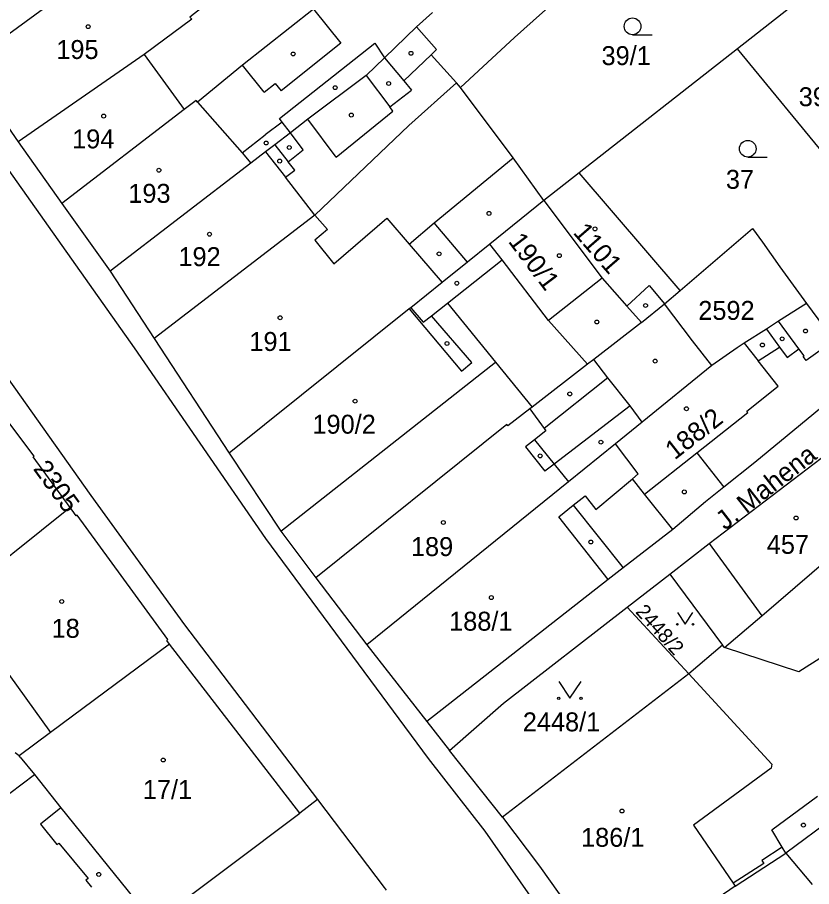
# Model space of a CAD drawing. Extents: x -679220 to -673243, y -1075091 to -1066557.
# Drawn here: x -676495.5 to -676424.2, y -1071396.5 to -1071318.5 of the extents above; entities that cross this region are included whole.
import ezdxf

# ---------------------------------------------------------------- set-up
doc = ezdxf.new("R2010")
doc.units = 0
for name, color, linetype in [('Hranice parcel', 7, 'Continuous'), ('Parcelní čísla', 7, 'Continuous'), ('Pop  PČ popisy', 7, 'Continuous'), ('Vnitřní kresba', 7, 'Continuous'), ('Značky budov', 7, 'Continuous'), ('Značky kultur', 7, 'Continuous')]:
    doc.layers.add(name, color=color, linetype=linetype)

msp = doc.modelspace()

# ---------------------------------------------------------------- linework, layer by layer
at = {"layer": 'Hranice parcel'}
for p, q in [((-676426.2, -1071317.64), (-676430.88, -1071321.3)), ((-676459.7, -1071319.33), (-676458.28, -1071318.06)), ((-676430.88, -1071321.3), (-676445.12, -1071332.45)), ((-676420.79, -1071333.62), (-676430.88, -1071321.3)), ((-676500.22, -1071322.85), (-676495.45, -1071329.66)), ((-676455.75, -1071324.77), (-676456.12, -1071324.37)), ((-676495.45, -1071329.66), (-676491.54, -1071335.21)), ((-676445.12, -1071332.45), (-676448.29, -1071334.93)), ((-676436.05, -1071343.02), (-676445.12, -1071332.45)), ((-676491.54, -1071335.21), (-676487.2, -1071341.29)), ((-676487.2, -1071341.29), (-676483.24, -1071347.33)), ((-676437.44, -1071344.22), (-676436.05, -1071343.02)), ((-676439.51, -1071345.88), (-676437.44, -1071344.22)), ((-676483.24, -1071347.33), (-676476.51, -1071357.62)), ((-676440.79, -1071371.46), (-676436.97, -1071368.48)), ((-676436.97, -1071368.48), (-676432.25, -1071374.85)), ((-676468.73, -1071368.83), (-676464.17, -1071374.82)), ((-676435.26, -1071377.43), (-676440.79, -1071371.46)), ((-676470.18, -1071389.94), (-676481.89, -1071374.77)), ((-676464.17, -1071374.82), (-676458.79, -1071381.72)), ((-676432.25, -1071374.85), (-676435.26, -1071377.43)), ((-676432.05, -1071375.08), (-676432.25, -1071374.85)), ((-676435.26, -1071377.43), (-676452, -1071390.3)), ((-676458.79, -1071381.72), (-676456.74, -1071384.32)), ((-676452, -1071390.3), (-676456.74, -1071384.32)), ((-676468.6, -1071388.71), (-676470.18, -1071389.94))]:
    msp.add_line(p, q, dxfattribs=at)
for points in [[(-676400.64, -1071480.43), (-676404.65, -1071473.51), (-676415.78, -1071453.37), (-676425.35, -1071436.91), (-676444.25, -1071404.92), (-676453.53, -1071391.57), (-676458.63, -1071385.05), (-676473.24, -1071365.27), (-676485.03, -1071348.15), (-676497.15, -1071331.02), (-676507.56, -1071316.17), (-676512.86, -1071309.51), (-676528.01, -1071291.25), (-676530.94, -1071288.81)], [(-676477.43, -1071306.13), (-676481.2, -1071308.93), (-676500.22, -1071322.85)], [(-676436.69, -1071307.58), (-676450.91, -1071320.28), (-676455.75, -1071324.77)], [(-676472.66, -1071312.61), (-676476.74, -1071315.84), (-676480.05, -1071318.46), (-676479.87, -1071318.65), (-676483.21, -1071321.14), (-676484.16, -1071321.81), (-676495.45, -1071329.66)], [(-676463.23, -1071313.31), (-676464.89, -1071314.65), (-676468.96, -1071317.75), (-676475.31, -1071322.79), (-676479.35, -1071326.09), (-676479.48, -1071325.94), (-676480.56, -1071326.77), (-676491.54, -1071335.21)], [(-676459.7, -1071319.33), (-676462.58, -1071322.11), (-676464.23, -1071323.7), (-676469.45, -1071327.64), (-676471.02, -1071328.86), (-676472.42, -1071329.92), (-676473.25, -1071330.56), (-676474.57, -1071331.57), (-676487.2, -1071341.29)], [(-676456.12, -1071324.37), (-676458.39, -1071321.84), (-676457.91, -1071321.38), (-676459.7, -1071319.33)], [(-676456.12, -1071324.37), (-676460.4, -1071328.18), (-676468.84, -1071336.26), (-676483.24, -1071347.33)], [(-676448.29, -1071334.93), (-676451.02, -1071331.11), (-676455.75, -1071324.77)], [(-676448.29, -1071334.93), (-676453.12, -1071338.84), (-676455.14, -1071340.47), (-676457.39, -1071342.3), (-676460.21, -1071344.56)], [(-676448.29, -1071334.93), (-676443.04, -1071341.91), (-676440.82, -1071344.41), (-676439.51, -1071345.88)], [(-676505.99, -1071337.37), (-676488.95, -1071361.42), (-676480.52, -1071373.04), (-676468.6, -1071388.71)], [(-676436.05, -1071343.02), (-676429.56, -1071337.44), (-676428.66, -1071338.68), (-676427.09, -1071340.88), (-676424.71, -1071344.18)], [(-676490.8, -1071362.5), (-676494.11, -1071357.94), (-676494.03, -1071357.88), (-676498.86, -1071351.49), (-676498.95, -1071351.57), (-676502.59, -1071346.77), (-676504.55, -1071344.1)], [(-676460.21, -1071344.56), (-676459.12, -1071345.87), (-676458.37, -1071345.28), (-676456.93, -1071344.14), (-676452.61, -1071349.45), (-676449.33, -1071353.49)], [(-676433.19, -1071349.75), (-676434.92, -1071347.53), (-676437.44, -1071344.22)], [(-676424.71, -1071344.18), (-676427.2, -1071345.77), (-676428.29, -1071346.48), (-676430.29, -1071347.75), (-676430.92, -1071348.16), (-676433.19, -1071349.75)], [(-676424.71, -1071344.18), (-676422.26, -1071347.51), (-676419.93, -1071350.69)], [(-676460.21, -1071344.56), (-676460.35, -1071344.67), (-676476.51, -1071357.62)], [(-676439.51, -1071345.88), (-676443.8, -1071349.21), (-676444.36, -1071349.64), (-676449.33, -1071353.49)], [(-676433.19, -1071349.75), (-676439.44, -1071354.83), (-676441.85, -1071356.78)], [(-676419.93, -1071350.69), (-676429.34, -1071358.47), (-676432.11, -1071360.68), (-676433.76, -1071362), (-676436.71, -1071364.46)], [(-676449.33, -1071353.49), (-676449.53, -1071353.65), (-676451.51, -1071355.18), (-676451.6, -1071355.06), (-676468.73, -1071368.83)], [(-676441.85, -1071356.78), (-676446.07, -1071360.2), (-676464.17, -1071374.82)], [(-676436.71, -1071364.46), (-676439.24, -1071361.3), (-676440.33, -1071359.93), (-676439.8, -1071359.49), (-676441.85, -1071356.78)], [(-676436.97, -1071368.48), (-676433.45, -1071365.74), (-676422.14, -1071357.11)], [(-676432.05, -1071375.08), (-676428.72, -1071372.23), (-676418.02, -1071363.05), (-676422.14, -1071357.11)], [(-676476.51, -1071357.62), (-676471.87, -1071364.61), (-676468.73, -1071368.83)], [(-676490.8, -1071362.5), (-676501.25, -1071370.87), (-676500.97, -1071371.22), (-676502.64, -1071372.57), (-676502.83, -1071373.8), (-676504.42, -1071374.83), (-676505.15, -1071375.35), (-676507.99, -1071377.37), (-676516.55, -1071383.23), (-676517, -1071383.54)], [(-676481.89, -1071374.77), (-676482.11, -1071374.43), (-676482.03, -1071374.36), (-676490.17, -1071363.18), (-676490.25, -1071363.24), (-676490.6, -1071362.75), (-676490.8, -1071362.5)], [(-676436.71, -1071364.46), (-676441.15, -1071367.91), (-676442.51, -1071368.97), (-676458.79, -1071381.72)], [(-676412.22, -1071369.94), (-676412.75, -1071369.24), (-676425.38, -1071377.27), (-676432.05, -1071375.08)], [(-676456.74, -1071384.32), (-676451.91, -1071380.07), (-676440.79, -1071371.46)], [(-676481.89, -1071374.77), (-676492.56, -1071382.71), (-676495.38, -1071384.8), (-676495.73, -1071384.52)], [(-676468.6, -1071388.71), (-676462.6, -1071396.62), (-676462.44, -1071396.87)], [(-676487.13, -1071403.19), (-676485, -1071401.31), (-676483.36, -1071399.7), (-676483.28, -1071399.8), (-676470.18, -1071389.94)], [(-676452, -1071390.3), (-676448.66, -1071394.7), (-676442.06, -1071404.02)], [(-676422.28, -1071390.36), (-676426.57, -1071393.54), (-676426.89, -1071393.01), (-676428.7, -1071394.19), (-676428.53, -1071394.46), (-676431.27, -1071396.25), (-676431.1, -1071396.49), (-676442.06, -1071404.02)]]:
    msp.add_lwpolyline(points, dxfattribs=at)
at = {"layer": 'Vnitřní kresba'}
for p, q in [((-676468.96, -1071317.75), (-676466.5, -1071320.79)), ((-676472, -1071327.57), (-676463.46, -1071320.79)), ((-676466.5, -1071320.79), (-676471.86, -1071325.09)), ((-676463.46, -1071320.79), (-676462.58, -1071322.11)), ((-676484.16, -1071321.81), (-676480.56, -1071326.77)), ((-676462.58, -1071322.11), (-676460.85, -1071324.18)), ((-676460.85, -1071324.18), (-676458.39, -1071321.84)), ((-676473.37, -1071325.19), (-676475.31, -1071322.79)), ((-676464.23, -1071323.7), (-676462.11, -1071326.53)), ((-676473.37, -1071325.19), (-676472.4, -1071324.42)), ((-676472.4, -1071324.42), (-676471.86, -1071325.09)), ((-676460.85, -1071324.18), (-676460.15, -1071325.03)), ((-676462.11, -1071326.53), (-676460.15, -1071325.03)), ((-676479.35, -1071326.09), (-676475.36, -1071330.66)), ((-676466.91, -1071331.04), (-676461.82, -1071326.9)), ((-676461.82, -1071326.9), (-676462.11, -1071326.53)), ((-676471.75, -1071327.89), (-676473.3, -1071329.04)), ((-676471.75, -1071327.89), (-676472, -1071327.57)), ((-676471.02, -1071328.86), (-676471.75, -1071327.89)), ((-676466.91, -1071331.04), (-676469.45, -1071327.64)), ((-676475.36, -1071330.66), (-676473.3, -1071329.04)), ((-676469.87, -1071330.38), (-676471.02, -1071328.86)), ((-676472.42, -1071329.92), (-676471.21, -1071331.46)), ((-676475.36, -1071330.66), (-676474.57, -1071331.57)), ((-676473.25, -1071330.56), (-676471.47, -1071332.84)), ((-676471.21, -1071331.46), (-676469.87, -1071330.38)), ((-676470.64, -1071332.2), (-676471.21, -1071331.46)), ((-676458.13, -1071336.94), (-676451.02, -1071331.11)), ((-676471.47, -1071332.84), (-676470.64, -1071332.2)), ((-676468.84, -1071336.26), (-676471.47, -1071332.84)), ((-676468.84, -1071336.26), (-676467.68, -1071337.53)), ((-676467.12, -1071340.61), (-676462.36, -1071336.52)), ((-676462.36, -1071336.52), (-676460.35, -1071338.85)), ((-676460.35, -1071338.85), (-676458.13, -1071336.94)), ((-676455.14, -1071340.47), (-676458.13, -1071336.94)), ((-676467.68, -1071337.53), (-676468.82, -1071338.5)), ((-676468.82, -1071338.5), (-676467.12, -1071340.61)), ((-676460.35, -1071338.85), (-676457.39, -1071342.3)), ((-676452.02, -1071340.27), (-676453.12, -1071338.84)), ((-676456.93, -1071344.14), (-676452.02, -1071340.27)), ((-676447.85, -1071345.71), (-676452.02, -1071340.27)), ((-676443.04, -1071341.91), (-676447.85, -1071345.71)), ((-676440.82, -1071344.41), (-676438.81, -1071342.56)), ((-676438.81, -1071342.56), (-676437.44, -1071344.22)), ((-676460.35, -1071344.67), (-676455.68, -1071350.26)), ((-676454.73, -1071349.47), (-676458.37, -1071345.28)), ((-676447.85, -1071345.71), (-676444.36, -1071349.64)), ((-676425.38, -1071348.25), (-676427.2, -1071345.77)), ((-676428.29, -1071346.48), (-676427.11, -1071348.09)), ((-676430.29, -1071347.75), (-676429.04, -1071349.34)), ((-676429.04, -1071349.34), (-676427.11, -1071348.09)), ((-676427.11, -1071348.09), (-676426.43, -1071349.02)), ((-676422.26, -1071347.51), (-676424.72, -1071349.31)), ((-676426.43, -1071349.02), (-676425.38, -1071348.25)), ((-676424.91, -1071348.89), (-676425.38, -1071348.25)), ((-676424.99, -1071348.95), (-676424.91, -1071348.89)), ((-676424.72, -1071349.31), (-676424.99, -1071348.95)), ((-676455.68, -1071350.26), (-676454.73, -1071349.47)), ((-676453.88, -1071350.45), (-676452.61, -1071349.45)), ((-676442.52, -1071350.86), (-676443.8, -1071349.21)), ((-676427.24, -1071351.61), (-676429.04, -1071349.34)), ((-676471.87, -1071364.61), (-676453.88, -1071350.45)), ((-676442.52, -1071350.86), (-676448.24, -1071355.4)), ((-676440.52, -1071353.38), (-676442.52, -1071350.86)), ((-676430.06, -1071353.84), (-676427.24, -1071351.61)), ((-676449.53, -1071353.65), (-676448.24, -1071355.4)), ((-676440.52, -1071353.38), (-676447.36, -1071358.6)), ((-676439.44, -1071354.83), (-676440.52, -1071353.38)), ((-676434.55, -1071357.59), (-676429.97, -1071353.96)), ((-676429.97, -1071353.96), (-676430.06, -1071353.84)), ((-676448.1, -1071355.6), (-676449.12, -1071356.41)), ((-676448.24, -1071355.4), (-676448.1, -1071355.6)), ((-676449.12, -1071356.41), (-676449.92, -1071357.05)), ((-676449.12, -1071356.41), (-676447.36, -1071358.6)), ((-676449.92, -1071357.05), (-676448.19, -1071359.23)), ((-676439.24, -1071361.3), (-676434.55, -1071357.59)), ((-676434.55, -1071357.59), (-676432.11, -1071360.68)), ((-676447.36, -1071358.6), (-676448.19, -1071359.23)), ((-676447.36, -1071358.6), (-676446.07, -1071360.2)), ((-676443.62, -1071362.67), (-676440.33, -1071359.93)), ((-676445.64, -1071362.29), (-676444.58, -1071361.45)), ((-676444.58, -1071361.45), (-676443.62, -1071362.67)), ((-676446.93, -1071363.33), (-676445.64, -1071362.29)), ((-676445.64, -1071362.29), (-676441.15, -1071367.91)), ((-676442.51, -1071368.97), (-676446.93, -1071363.33)), ((-676433.45, -1071365.74), (-676428.72, -1071372.23)), ((-676496.99, -1071376.54), (-676492.56, -1071382.71)), ((-676435.26, -1071377.43), (-676427.82, -1071385.55)), ((-676495.27, -1071384.93), (-676495.38, -1071384.8)), ((-676495.27, -1071384.93), (-676493.98, -1071386.48)), ((-676427.82, -1071385.55), (-676427.88, -1071385.92)), ((-676497.52, -1071389.12), (-676493.98, -1071386.48)), ((-676493.98, -1071386.48), (-676491.63, -1071389.47)), ((-676427.88, -1071385.92), (-676434.84, -1071391.04)), ((-676427.81, -1071391.46), (-676423.72, -1071388.42)), ((-676491.63, -1071389.47), (-676493.46, -1071390.94)), ((-676491.63, -1071389.47), (-676483.36, -1071399.7)), ((-676493.46, -1071390.94), (-676491.99, -1071392.76)), ((-676434.84, -1071391.04), (-676431.27, -1071396.25)), ((-676426.89, -1071393.01), (-676427.81, -1071391.46)), ((-676491.99, -1071392.76), (-676491.82, -1071392.63)), ((-676491.82, -1071392.63), (-676489.19, -1071395.82)), ((-676431.1, -1071396.49), (-676426.57, -1071393.54)), ((-676426.57, -1071393.54), (-676424.19, -1071396.35)), ((-676489.19, -1071395.82), (-676489.39, -1071395.97)), ((-676489.39, -1071395.97), (-676488.87, -1071396.6))]:
    msp.add_line(p, q, dxfattribs=at)
at = {"layer": 'Značky budov'}
for centre in [(-676489.177, -1071319.319), (-676470.777, -1071321.769), (-676460.197, -1071321.709), (-676467.007, -1071324.799), (-676462.207, -1071324.419), (-676465.557, -1071327.259), (-676487.787, -1071327.349), (-676473.197, -1071329.769), (-676471.127, -1071330.169), (-676471.987, -1071331.389), (-676482.827, -1071332.209), (-676453.197, -1071336.089), (-676443.687, -1071337.479), (-676478.287, -1071337.959), (-676457.677, -1071339.719), (-676446.887, -1071339.879), (-676456.087, -1071342.359), (-676439.147, -1071344.359), (-676471.947, -1071345.459), (-676443.517, -1071345.839), (-676424.787, -1071346.649), (-676426.887, -1071347.349), (-676456.967, -1071347.769), (-676428.657, -1071347.909), (-676438.287, -1071349.349), (-676445.947, -1071352.299), (-676465.217, -1071352.949), (-676435.477, -1071353.629), (-676443.157, -1071356.629), (-676448.607, -1071357.869), (-676435.667, -1071361.099), (-676457.297, -1071363.849), (-676425.637, -1071363.439), (-676444.057, -1071365.599), (-676491.547, -1071370.939), (-676452.987, -1071370.589), (-676482.437, -1071385.179), (-676441.257, -1071389.759), (-676424.977, -1071391.019), (-676488.227, -1071395.449)]:
    msp.add_circle(centre, 0.175, dxfattribs=at)
at = {"layer": 'Značky kultur'}
for p, q in [((-676440.313, -1071320.04), (-676438.563, -1071320.04)), ((-676429.973, -1071331.03), (-676428.223, -1071331.03))]:
    msp.add_line(p, q, dxfattribs=at)
for points in [[(-676436.29, -1071371.939), (-676435.59, -1071372.99), (-676434.89, -1071371.939)], [(-676446.94, -1071378.129), (-676445.94, -1071379.63), (-676444.94, -1071378.129)]]:
    msp.add_lwpolyline(points, dxfattribs=at)
for centre, radius in [((-676440.313, -1071319.29), 0.75), ((-676429.973, -1071330.28), 0.75), ((-676436.29, -1071372.99), 0.07), ((-676434.89, -1071372.99), 0.07), ((-676446.94, -1071379.629), 0.1), ((-676444.94, -1071379.629), 0.1)]:
    msp.add_circle(centre, radius, dxfattribs=at)

# ---------------------------------------------------------------- texts
at = {"layer": 'Parcelní čísla'}
for s, p in [('195', (-676492.035, -1071322.22)), ('39/1', (-676443.099, -1071322.769)), ('39/3', (-676425.399, -1071326.46)), ('194', (-676490.615, -1071330.249)), ('37', (-676431.936, -1071333.88)), ('193', (-676485.575, -1071335.14)), ('192', (-676481.075, -1071340.82)), ('2592', (-676434.414, -1071345.65)), ('191', (-676474.705, -1071348.44)), ('190/2', (-676469.048, -1071355.87)), ('189', (-676460.205, -1071366.86)), ('457', (-676428.265, -1071366.66)), ('188/1', (-676456.778, -1071373.56)), ('18', (-676492.46, -1071374.2)), ('2448/1', (-676450.167, -1071382.6)), ('17/1', (-676484.27, -1071388.67)), ('186/1', (-676444.938, -1071392.97))]:
    msp.add_text(s, height=1.7, dxfattribs=at).set_placement(p)
for s, height, rotation, p in [('1101', 1.7, 311, (-676445.722, -1071337.842)), ('190/1', 1.7, 307, (-676451.533, -1071338.617)), ('188/2', 1.7, 38, (-676436.535, -1071358.28)), ('2305', 1.7, 306, (-676494.167, -1071359.029)), ('2448/2', 1.3, 312, (-676440.113, -1071371.911))]:
    msp.add_text(s, height=height, rotation=rotation, dxfattribs=at).set_placement(p)
at = {"layer": 'Pop  PČ popisy'}
msp.add_text('J. Mahena', height=1.7, rotation=38, dxfattribs=at).set_placement((-676432.004, -1071364.591))

doc.saveas('drawing.dxf')
